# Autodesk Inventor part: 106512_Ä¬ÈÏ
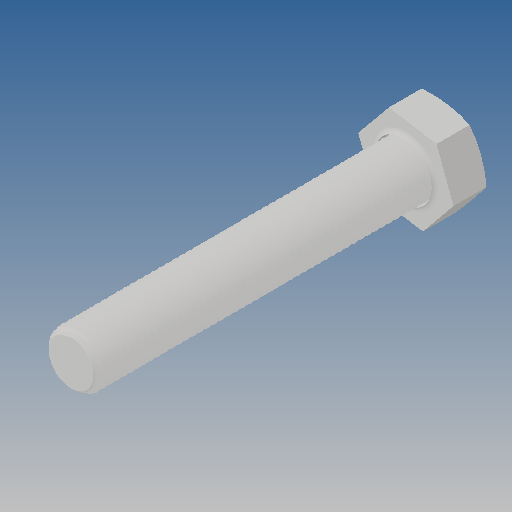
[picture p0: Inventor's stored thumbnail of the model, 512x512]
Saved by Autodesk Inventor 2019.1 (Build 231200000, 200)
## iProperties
Created: 2010-06
Part Number: 106512_Ä¬ÈÏ
Material: Ogólny
Document SubType Name: Modeling
Designer: CADENGINEERING4
Density: 1 g/cm^3
Appearance: Domyślna
Author: CADENGINEERING4
Revision Number: ÈÎºÎ
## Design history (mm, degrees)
feature "NONE"
node "Bryła1"
